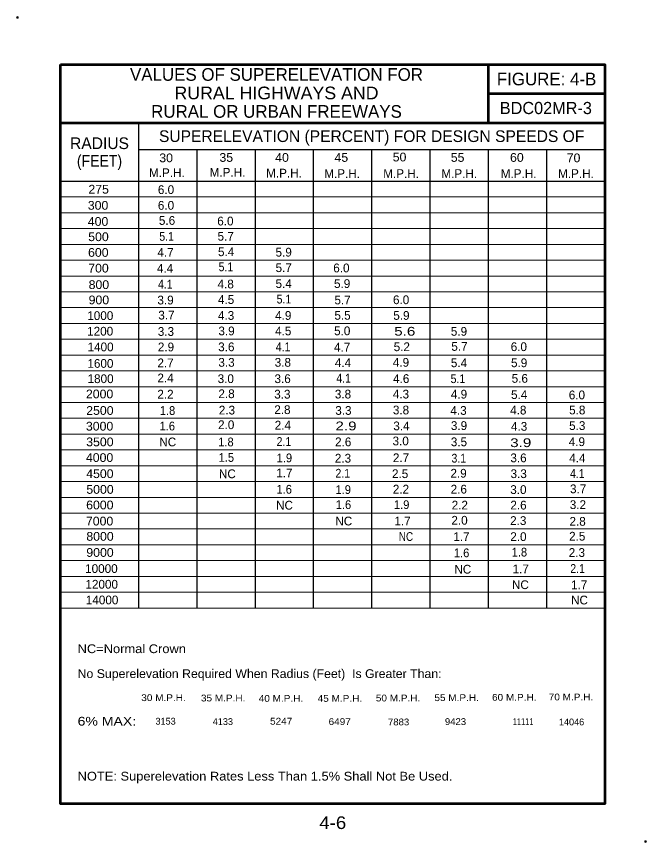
# Model space of a CAD drawing. Extents: x -1.77 to -0.92, y 1.68 to 2.79.
import ezdxf
from ezdxf.enums import TextEntityAlignment as Align

# ---------------------------------------------------------------- set-up
doc = ezdxf.new("R2010")
doc.units = 0
doc.header["$LTSCALE"] = 0.0047
doc.header["$PDMODE"] = 32
doc.header["$PDSIZE"] = 0.00235
doc.layers.add('1', color=7, linetype='Continuous', lineweight=13)

msp = doc.modelspace()

# ---------------------------------------------------------------- linework, layer by layer
at = {"layer": '1', "lineweight": 53}
for p, q in [((-1.136719, 2.723781), (-1.136719, 2.645656)), ((-1.136719, 2.684719), (-0.980469, 2.684719)), ((-1.709635, 2.645656), (-0.980469, 2.645656))]:
    msp.add_line(p, q, dxfattribs=at)
at = {"layer": '1', "lineweight": 25}
for p, q in [((-1.605469, 2.645656), (-1.605469, 1.99624)), ((-1.605469, 2.609844), (-0.980469, 2.609844)), ((-1.527344, 2.609844), (-1.527344, 1.99624)), ((-1.449219, 2.609844), (-1.449219, 1.99624)), ((-1.371094, 2.609844), (-1.371094, 1.99624)), ((-1.292969, 2.609844), (-1.292969, 1.99624)), ((-1.214844, 2.609844), (-1.214844, 1.99624)), ((-1.136719, 2.609844), (-1.136719, 1.99624)), ((-1.058594, 2.609844), (-1.058594, 1.99624)), ((-1.709635, 2.567531), (-0.980469, 2.567531))]:
    msp.add_line(p, q, dxfattribs=at)
at = {"layer": '1'}
for p, q in [((-1.709885, 2.546365), (-0.980469, 2.546365)), ((-1.709885, 2.525208), (-0.980469, 2.525208)), ((-1.709885, 2.504052), (-0.980469, 2.504052)), ((-1.709885, 2.482896), (-0.980469, 2.482896)), ((-1.709885, 2.461729), (-0.980469, 2.461729)), ((-1.709885, 2.440573), (-0.980469, 2.440573)), ((-1.709885, 2.419417), (-0.980469, 2.419417)), ((-1.709885, 2.39826), (-0.980469, 2.39826)), ((-1.709885, 2.377094), (-0.980469, 2.377094)), ((-1.709885, 2.355938), (-0.980469, 2.355938)), ((-1.709885, 2.334781), (-0.980469, 2.334781)), ((-1.709885, 2.313625), (-0.980469, 2.313625)), ((-1.709885, 2.292458), (-0.980469, 2.292458)), ((-1.709885, 2.271302), (-0.980469, 2.271302)), ((-1.709885, 2.250146), (-0.980469, 2.250146)), ((-1.709885, 2.22899), (-0.980469, 2.22899)), ((-1.709885, 2.207823), (-0.980469, 2.207823)), ((-1.709885, 2.186667), (-0.980469, 2.186667)), ((-1.709885, 2.16551), (-0.980469, 2.16551)), ((-1.709885, 2.144354), (-0.980469, 2.144354)), ((-1.709885, 2.123187), (-0.980469, 2.123187)), ((-1.709885, 2.102031), (-0.980469, 2.102031)), ((-1.709885, 2.080875), (-0.980469, 2.080875)), ((-1.709885, 2.059719), (-0.980469, 2.059719)), ((-1.709885, 2.038552), (-0.980469, 2.038552)), ((-1.709885, 2.017396), (-0.980469, 2.017396)), ((-1.709885, 1.99624), (-0.980469, 1.99624))]:
    msp.add_line(p, q, dxfattribs=at)
at = {"layer": '1', "lineweight": 53}
msp.add_lwpolyline([(-1.709635, 2.723781), (-0.980469, 2.723781), (-0.980469, 1.734198), (-1.709635, 1.734198)], close=True, dxfattribs=at)
at = {"layer": '1'}
for p in [(-1.767583, 2.786719), (-0.925917, 1.683594)]:
    msp.add_point(p, dxfattribs=at)

# ---------------------------------------------------------------- texts
for s, height, p in [('VALUES OF SUPERELEVATION FOR', 0.01693, (-1.420443, 2.701865)), ('FIGURE: 4-B', 0.01692, (-1.058594, 2.695792)), ('RURAL OR URBAN FREEWAYS', 0.01693, (-1.420443, 2.652385)), ('BDC02MR-3', 0.01628, (-1.059578, 2.657312)), ('SUPERELEVATION (PERCENT) FOR DESIGN SPEEDS OF', 0.01562, (-1.292974, 2.619937)), ('RADIUS', 0.01562, (-1.657552, 2.6105)), ('M.P.H.', 0.01172, (-1.567286, 2.572958)), ('M.P.H.', 0.01172, (-1.486078, 2.57351)), ('M.P.H.', 0.01172, (-1.410391, 2.572417)), ('M.P.H.', 0.01172, (-1.332495, 2.571854)), ('M.P.H.', 0.01172, (-1.253495, 2.571854)), ('M.P.H.', 0.01172, (-1.175599, 2.571854)), ('M.P.H.', 0.01172, (-1.096047, 2.571854)), ('M.P.H.', 0.01172, (-1.019255, 2.571854)), ('6.0', 0.01172, (-1.568464, 2.550312)), ('6.0', 0.01172, (-1.568464, 2.529292)), ('5.6', 0.01172, (-1.567078, 2.509083)), ('6.0', 0.01172, (-1.488911, 2.508292)), ('5.7', 0.01172, (-1.488479, 2.487917)), ('4.7', 0.01172, (-1.569073, 2.466469)), ('5.4', 0.01172, (-1.487911, 2.467188)), ('5.9', 0.01172, (-1.410802, 2.466615)), ('4.4', 0.01172, (-1.569661, 2.445156)), ('5.7', 0.01172, (-1.410771, 2.445875)), ('6.0', 0.01172, (-1.333495, 2.445521)), ('4.8', 0.01172, (-1.4885, 2.424)), ('5.4', 0.01172, (-1.410776, 2.424573)), ('5.9', 0.01172, (-1.332521, 2.424573)), ('3.9', 0.01172, (-1.569094, 2.402542)), ('4.5', 0.01172, (-1.487969, 2.40325)), ('5.7', 0.01172, (-1.331917, 2.402677)), ('6.0', 0.01172, (-1.253484, 2.402906)), ('1000', 0.01172, (-1.656484, 2.381719)), ('3.7', 0.01172, (-1.567927, 2.382385)), ('4.3', 0.01172, (-1.487964, 2.381948)), ('4.9', 0.01172, (-1.411375, 2.381948)), ('5.5', 0.01172, (-1.331979, 2.382083)), ('5.9', 0.01172, (-1.253083, 2.381948)), ('1200', 0.01172, (-1.656672, 2.360844)), ('3.3', 0.01172, (-1.568557, 2.36049)), ('3.9', 0.01172, (-1.487365, 2.361208)), ('4.5', 0.01172, (-1.411406, 2.361208)), ('5.0', 0.01172, (-1.332391, 2.361354)), ('5.9', 0.01172, (-1.175958, 2.360635)), ('1400', 0.01172, (-1.656109, 2.339844)), ('2.9', 0.01172, (-1.568521, 2.33976)), ('3.6', 0.01172, (-1.487641, 2.339906)), ('4.7', 0.01172, (-1.33249, 2.339469)), ('5.2', 0.01172, (-1.252557, 2.340042)), ('5.7', 0.01172, (-1.175354, 2.340479)), ('6.0', 0.01172, (-1.095755, 2.340115)), ('1600', 0.01172, (-1.656328, 2.317729)), ('2.7', 0.01172, (-1.569073, 2.318448)), ('3.3', 0.01172, (-1.487391, 2.319167)), ('3.8', 0.01172, (-1.411937, 2.319167)), ('4.4', 0.01172, (-1.331339, 2.31874)), ('4.9', 0.01172, (-1.253656, 2.319167)), ('5.4', 0.01172, (-1.175922, 2.318594)), ('5.9', 0.01172, (-1.095375, 2.318594)), ('1800', 0.01172, (-1.656109, 2.297281)), ('2.4', 0.01172, (-1.569078, 2.298292)), ('3.0', 0.01172, (-1.48838, 2.297292)), ('3.6', 0.01172, (-1.412224, 2.297292)), ('4.6', 0.01172, (-1.253349, 2.297417)), ('5.6', 0.01172, (-1.094484, 2.297719)), ('2.2', 0.01172, (-1.569151, 2.276552)), ('2.8', 0.01172, (-1.487354, 2.277135)), ('3.3', 0.01172, (-1.412568, 2.276552)), ('3.8', 0.01172, (-1.331354, 2.276687)), ('4.3', 0.01172, (-1.253682, 2.276687)), ('4.9', 0.01172, (-1.175937, 2.276552)), ('5.4', 0.01172, (-1.095339, 2.275979)), ('6.0', 0.01172, (-1.017974, 2.275583)), ('2.3', 0.01172, (-1.486818, 2.25525)), ('2.8', 0.01172, (-1.412531, 2.255823)), ('3.3', 0.01172, (-1.330818, 2.254802)), ('3.8', 0.01172, (-1.253646, 2.255375)), ('4.3', 0.01172, (-1.176547, 2.254802)), ('4.8', 0.01172, (-1.0965, 2.25525)), ('5.8', 0.01172, (-1.0175, 2.255385)), ('2.0', 0.01172, (-1.487807, 2.235667)), ('2.4', 0.01172, (-1.411922, 2.235094)), ('3.4', 0.01172, (-1.253057, 2.234073)), ('3.9', 0.01172, (-1.175948, 2.2345)), ('4.3', 0.01172, (-1.095391, 2.2335)), ('5.3', 0.01172, (-1.017536, 2.2345)), ('NC', 0.01172, (-1.566115, 2.212625)), ('2.6', 0.01172, (-1.331057, 2.21276)), ('3.0', 0.01172, (-1.254089, 2.213917)), ('3.5', 0.01172, (-1.175979, 2.21276)), ('4.9', 0.01172, (-1.01799, 2.212958)), ('2.3', 0.01172, (-1.331391, 2.190885)), ('2.7', 0.01172, (-1.253625, 2.191458)), ('3.6', 0.01172, (-1.096193, 2.191323)), ('4.4', 0.01172, (-1.01737, 2.191083)), ('NC', 0.01172, (-1.486271, 2.17001)), ('1.7', 0.01172, (-1.409865, 2.171156)), ('2.5', 0.01172, (-1.254844, 2.170146)), ('2.9', 0.01172, (-1.176521, 2.170719)), ('3.3', 0.01172, (-1.095964, 2.170146)), ('2.2', 0.01172, (-1.253703, 2.149417)), ('2.6', 0.01172, (-1.176214, 2.149417)), ('3.0', 0.01172, (-1.09637, 2.148844)), ('3.7', 0.01172, (-1.016312, 2.149844)), ('NC', 0.01172, (-1.409708, 2.127969)), ('2.2', 0.01172, (-1.174839, 2.128094)), ('2.6', 0.01172, (-1.096203, 2.128115)), ('3.2', 0.01172, (-1.01662, 2.128687)), ('NC', 0.01172, (-1.330281, 2.106792)), ('1.7', 0.01172, (-1.251573, 2.106792)), ('2.0', 0.01172, (-1.175224, 2.107802)), ('2.3', 0.01172, (-1.096536, 2.107365)), ('2.8', 0.01172, (-1.017031, 2.106375)), ('1.7', 0.01172, (-1.172708, 2.085927)), ('2.0', 0.01172, (-1.096359, 2.085906)), ('2.5', 0.01172, (-1.017542, 2.086448)), ('2.3', 0.01172, (-1.018016, 2.064625)), ('10000', 0.01172, (-1.655, 2.043146)), ('NC', 0.01172, (-1.170833, 2.042292)), ('1.7', 0.01172, (-1.09326, 2.042719)), ('12000', 0.01172, (-1.654615, 2.022146)), ('NC', 0.01172, (-1.093698, 2.021562)), ('1.7', 0.01172, (-1.014958, 2.021427)), ('14000', 0.01172, (-1.654073, 2.001146)), ('NC', 0.01172, (-1.01449, 2.001031)), ('3153', 0.009104, (-1.569031, 1.840156)), ('4133', 0.009104, (-1.492281, 1.839656)), ('14046', 0.009104, (-1.025156, 1.839177))]:
    msp.add_text(s, height=height, dxfattribs=at).set_placement(p, align=Align.CENTER)
for s, height, width, p in [('RURAL HIGHWAYS AND', 0.01693, 1.05, (-1.420438, 2.677125)), ('(FEET)', 0.01562, 0.9, (-1.657557, 2.587063)), ('30', 0.01172, 1.05, (-1.568286, 2.592854)), ('35', 0.01172, 1.05, (-1.487729, 2.593417)), ('40', 0.01172, 1.05, (-1.413057, 2.593417)), ('45', 0.01172, 1.05, (-1.333583, 2.593417)), ('50', 0.01172, 1.05, (-1.255589, 2.593958)), ('55', 0.01172, 1.05, (-1.177792, 2.593417)), ('60', 0.01172, 1.05, (-1.098401, 2.593417)), ('70', 0.01172, 1.05, (-1.022464, 2.592854)), ('275', 0.01172, 1.05, (-1.658708, 2.550854)), ('300', 0.01172, 1.05, (-1.659484, 2.529292)), ('400', 0.01172, 1.05, (-1.659484, 2.50775)), ('500', 0.01172, 1.05, (-1.658932, 2.487292)), ('5.1', 0.01172, 0.9, (-1.56763, 2.487771)), ('600', 0.01172, 1.05, (-1.659151, 2.466292)), ('700', 0.01172, 1.05, (-1.658932, 2.445281)), ('5.1', 0.01172, 0.9, (-1.488203, 2.447031)), ('800', 0.01172, 1.05, (-1.65838, 2.423177)), ('4.1', 0.01172, 0.9, (-1.56937, 2.423854)), ('900', 0.01172, 1.05, (-1.65838, 2.402719)), ('5.1', 0.01172, 0.9, (-1.410484, 2.403823)), ('5.6', 0.01172, 1.3, (-1.248583, 2.360771)), ('4.1', 0.01172, 0.9, (-1.411641, 2.339906)), ('4.1', 0.01172, 0.9, (-1.330484, 2.29801)), ('5.1', 0.01172, 0.9, (-1.177359, 2.297292)), ('2000', 0.01172, 1.05, (-1.657437, 2.276833)), ('2500', 0.01172, 1.05, (-1.657052, 2.254729)), ('1.8', 0.01172, 0.95, (-1.566458, 2.254677)), ('3000', 0.01172, 1.05, (-1.657437, 2.233708)), ('1.6', 0.01172, 0.95, (-1.566734, 2.233927)), ('2.9', 0.01172, 1.3, (-1.327344, 2.234073)), ('3500', 0.01172, 1.05, (-1.657052, 2.212708)), ('1.8', 0.01172, 0.95, (-1.488167, 2.212625)), ('2.1', 0.01172, 0.9, (-1.410484, 2.213198)), ('3.9', 0.01172, 1.3, (-1.093208, 2.211615)), ('4000', 0.01172, 1.05, (-1.657437, 2.191708)), ('1.5', 0.01172, 0.95, (-1.487635, 2.191885)), ('1.9', 0.01172, 0.95, (-1.409885, 2.191312)), ('3.1', 0.01172, 0.9, (-1.176214, 2.190885)), ('4500', 0.01172, 1.05, (-1.657052, 2.170156)), ('2.1', 0.01172, 0.9, (-1.33163, 2.170719)), ('4.1', 0.01172, 0.9, (-1.017453, 2.170354)), ('5000', 0.01172, 1.05, (-1.656896, 2.149135)), ('1.6', 0.01172, 0.95, (-1.410151, 2.149271)), ('1.9', 0.01172, 0.95, (-1.331031, 2.148844)), ('6000', 0.01172, 1.05, (-1.657125, 2.128281)), ('1.6', 0.01172, 0.95, (-1.330724, 2.128687)), ('1.9', 0.01172, 0.95, (-1.25275, 2.128687)), ('7000', 0.01172, 1.05, (-1.657437, 2.106719)), ('8000', 0.01172, 1.05, (-1.656896, 2.08626)), ('NC', 0.01172, 0.85, (-1.247, 2.086052)), ('9000', 0.01172, 1.05, (-1.656896, 2.064708)), ('1.6', 0.01172, 0.95, (-1.172432, 2.064177)), ('1.8', 0.01172, 0.95, (-1.095021, 2.065177)), ('2.1', 0.01172, 0.9, (-1.016995, 2.04325)), ('30 M.P.H.', 0.009104, 1.1, (-1.571807, 1.871667)), ('35 M.P.H.', 0.009104, 1.1, (-1.49188, 1.871188)), ('40 M.P.H.', 0.009104, 1.1, (-1.414464, 1.870698)), ('45 M.P.H.', 0.009104, 1.1, (-1.335495, 1.870698)), ('50 M.P.H.', 0.009104, 1.1, (-1.257589, 1.871188)), ('55 M.P.H.', 0.009104, 1.1, (-1.179109, 1.871667)), ('60 M.P.H.', 0.009104, 1.1, (-1.101922, 1.872146)), ('70 M.P.H.', 0.009104, 1.1, (-1.025911, 1.872625)), ('5247', 0.009104, 1.1, (-1.414167, 1.840156)), ('6497', 0.009104, 1.1, (-1.335729, 1.839656)), ('7883', 0.009104, 1.05, (-1.25687, 1.839177)), ('9423', 0.009104, 1.05, (-1.18062, 1.839656)), ('11111', 0.009104, 0.75, (-1.090005, 1.839656)), ('4-6', 0.01692, 1.1, (-1.345052, 1.700438))]:
    msp.add_text(s, height=height, dxfattribs=dict(at, width=width)).set_placement(p, align=Align.CENTER)
for s, width, p in [('NC=Normal Crown', 1.1, (-1.686885, 1.935865)), ('No Superelevation Required When Radius (Feet)  Is Greater Than:', 1.05, (-1.686885, 1.902531)), ('6% MAX:', 1.2, (-1.686885, 1.838844)), ('NOTE: Superelevation Rates Less Than 1.5% Shall Not Be Used.', 1.1, (-1.686885, 1.765302))]:
    msp.add_text(s, height=0.01172, dxfattribs=dict(at, width=width)).set_placement(p)

doc.saveas('drawing.dxf')
